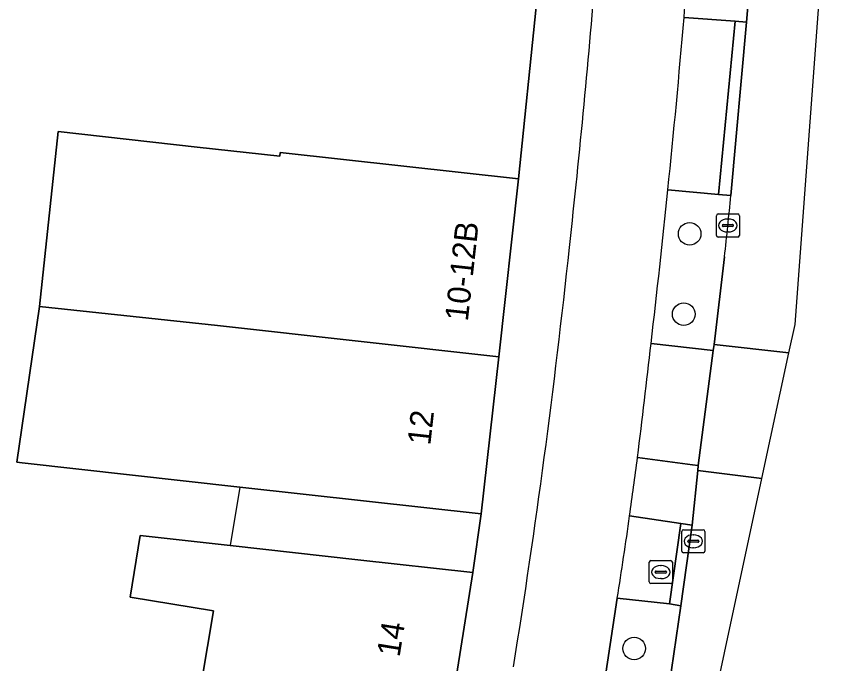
# Model space of a CAD drawing. Extents: x 161087 to 161926, y 382572 to 383873.
# Drawn here: x 161833.12 to 161869.18, y 382703.67 to 382731.66 of the extents above; entities that cross this region are included whole.
import ezdxf

# ---------------------------------------------------------------- set-up
doc = ezdxf.new("R2010")
doc.units = 0
for name, color, linetype in [('IMGEO_Berm_gesloten', 7, 'Continuous'), ('IMGEO_Berm_groen', 7, 'Continuous'), ('IMGEO_Berm_open', 7, 'Continuous'), ('IMGEO_Boom', 7, 'Continuous'), ('IMGEO_Erf', 7, 'Continuous'), ('IMGEO_Fietspad_gesloten', 7, 'Continuous'), ('IMGEO_Kolk', 7, 'Continuous'), ('IMGEO_Pand', 7, 'Continuous'), ('IMGEO_Pand_nummerreeks', 7, 'Continuous'), ('IMGEO_Pand_overbouw', 7, 'Continuous'), ('IMGEO_Rijbaan_lokaal_gesloten', 7, 'Continuous'), ('IMGEO_Rijbaan_lokaal_open', 7, 'Continuous'), ('IMGEO_Rioolput', 7, 'Continuous'), ('IMGEO_Voetpad_open', 7, 'Continuous')]:
    doc.layers.add(name, color=color, linetype=linetype)

msp = doc.modelspace()

# ---------------------------------------------------------------- linework, layer by layer
at = {"layer": 'IMGEO_Berm_gesloten'}
for points in [[(161864.696, 382731.416), (161864.202, 382731.46), (161863.482, 382723.956), (161864.006, 382723.914)], [(161862.334, 382709.651), (161861.851, 382709.721), (161861.36, 382706.245), (161861.855, 382706.161)]]:
    msp.add_lwpolyline(points, close=True, dxfattribs=at)
at = {"layer": 'IMGEO_Berm_groen'}
for points in [[(161861.988, 382731.623), (161864.202, 382731.46), (161864.696, 382731.416), (161864.916, 382734.182), (161865.365, 382740.966)], [(161864.202, 382731.46), (161861.988, 382731.623)], [(161861.289, 382724.163), (161863.482, 382723.956), (161864.202, 382731.46)], [(161864.006, 382723.914), (161863.482, 382723.956), (161861.289, 382724.163)], [(161860.56, 382717.514), (161863.253, 382717.214), (161863.287, 382717.469), (161863.737, 382721.269)], [(161862.582, 382712.012), (161862.605, 382712.233), (161862.359, 382712.264), (161859.973, 382712.583)], [(161859.633, 382710.052), (161861.851, 382709.721), (161862.334, 382709.651), (161862.582, 382712.012)]]:
    msp.add_lwpolyline(points, dxfattribs=at)
msp.add_lwpolyline([(161861.855, 382706.161), (161861.36, 382706.245), (161859.099, 382706.489), (161858.483, 382702.48), (161861.244, 382702.01)], close=True, dxfattribs=at)
for centre, radius, start, end in [((161450.001, 382766.972), 413.501, 355.09598, 355.73945), ((161429.341, 382768.399), 434.207, 354.15268, 355.14138), ((161419.334, 382769.255), 444.249, 353.31171, 354.17439), ((161780.577, 382731.063), 83.735, 353.28328, 355.10254), ((161621.237, 382743.365), 240.713, 352.04509, 352.65295)]:
    msp.add_arc(centre, radius, start, end, dxfattribs=at)
at = {"layer": 'IMGEO_Berm_open'}
for points in [[(161859.973, 382712.583), (161862.359, 382712.264), (161862.605, 382712.233), (161863.253, 382717.214)], [(161863.253, 382717.214), (161860.56, 382717.514)], [(161861.851, 382709.721), (161859.633, 382710.052)], [(161859.099, 382706.489), (161861.36, 382706.245), (161861.851, 382709.721)]]:
    msp.add_lwpolyline(points, dxfattribs=at)
for centre, radius, start, end in [((161529.822, 382754.385), 332.787, 352.78381, 353.63878), ((161657.287, 382738.557), 204.344, 350.97121, 351.98141)]:
    msp.add_arc(centre, radius, start, end, dxfattribs=at)
at = {"layer": 'IMGEO_Boom'}
for centre in [(161862.23, 382722.257), (161861.973, 382718.78), (161859.833, 382704.313)]:
    msp.add_circle(centre, 0.489, dxfattribs=at)
at = {"layer": 'IMGEO_Erf'}
msp.add_lwpolyline([(161841.12, 382702.859), (161841.626, 382705.941), (161838.025, 382706.533), (161838.463, 382709.199), (161842.351, 382708.766), (161847.875, 382708.151), (161852.844, 382707.598), (161853.217, 382710.138), (161848.248, 382710.691), (161842.767, 382711.301), (161833.36, 382712.347), (161833.118, 382712.374), (161834.103, 382719.118), (161834.908, 382726.684), (161840.922, 382726.017), (161844.498, 382725.62), (161844.517, 382725.785), (161849.862, 382725.191), (161854.831, 382724.638), (161855.594, 382732.092)], dxfattribs=at)
at = {"layer": 'IMGEO_Fietspad_gesloten'}
msp.add_lwpolyline([(161857.735, 382697.596), (161858.483, 382702.48), (161859.099, 382706.489)], dxfattribs=at)
for centre, radius, start, end in [((161450.001, 382766.972), 413.501, 355.09598, 355.73945), ((161443.323, 382767.161), 416.2, 353.72536, 355.4368), ((161429.341, 382768.399), 434.207, 354.15268, 355.14138), ((161419.334, 382769.255), 444.249, 353.31171, 354.17439), ((161515.74, 382757.93), 343.21, 350.8781, 353.93592), ((161529.822, 382754.385), 332.787, 352.78381, 353.63878), ((161621.237, 382743.365), 240.713, 352.04509, 352.65295), ((161657.287, 382738.557), 204.344, 350.97121, 351.98141)]:
    msp.add_arc(centre, radius, start, end, dxfattribs=at)
at = {"layer": 'IMGEO_Kolk'}
for p, q in [((161863.384, 382722.194), (161863.384, 382723.046)), ((161863.459, 382723.12), (161864.311, 382723.12)), ((161864.385, 382723.046), (161864.385, 382722.194)), ((161863.643, 382722.614), (161863.643, 382722.626)), ((161863.686, 382722.663), (161864.084, 382722.663)), ((161863.872, 382722.9), (161863.897, 382722.9)), ((161864.127, 382722.626), (161864.127, 382722.614)), ((161864.081, 382722.577), (161863.683, 382722.577)), ((161863.895, 382722.34), (161863.87, 382722.34)), ((161864.311, 382722.12), (161863.459, 382722.12)), ((161861.888, 382708.528), (161861.888, 382709.38)), ((161861.963, 382709.454), (161862.815, 382709.454)), ((161862.889, 382709.38), (161862.889, 382708.528)), ((161862.147, 382708.948), (161862.147, 382708.96)), ((161862.585, 382708.911), (161862.187, 382708.911)), ((161862.19, 382708.997), (161862.588, 382708.997)), ((161862.376, 382709.234), (161862.401, 382709.234)), ((161862.631, 382708.96), (161862.631, 382708.948)), ((161862.399, 382708.674), (161862.374, 382708.674)), ((161862.815, 382708.454), (161861.963, 382708.454))]:
    msp.add_line(p, q, dxfattribs=at)
for points in [[(161863.384, 382722.194), (161863.384, 382723.046)], [(161863.459, 382723.12), (161864.311, 382723.12)], [(161864.385, 382723.046), (161864.385, 382722.194)], [(161864.311, 382722.12), (161863.459, 382722.12)], [(161861.888, 382708.528), (161861.888, 382709.38)], [(161861.963, 382709.454), (161862.815, 382709.454)], [(161862.889, 382709.38), (161862.889, 382708.528)], [(161862.815, 382708.454), (161861.963, 382708.454)]]:
    msp.add_lwpolyline(points, dxfattribs=at)
for centre, radius, start, end in [((161863.461, 382723.044), 0.0765, 91.552, 178.448), ((161863.461, 382723.044), 0.0765, 91.552, 178.448), ((161864.309, 382723.044), 0.0765, 1.552, 88.448), ((161864.309, 382723.044), 0.0765, 1.552, 88.448), ((161863.683, 382722.623), 0.0403, 85.8775, 175.7526), ((161863.68, 382722.613), 0.0366, 178.938, 274.7102), ((161864.084, 382722.62), 0.043, 264.8664, 352.4533), ((161864.088, 382722.625), 0.0386, 1.7309, 96.639), ((161863.461, 382722.196), 0.0765, 181.552, 268.448), ((161863.461, 382722.196), 0.0765, 181.552, 268.448), ((161864.309, 382722.196), 0.0765, 271.552, 358.448), ((161864.309, 382722.196), 0.0765, 271.552, 358.448), ((161861.965, 382709.378), 0.0765, 91.552, 178.448), ((161861.965, 382709.378), 0.0765, 91.552, 178.448), ((161862.813, 382709.378), 0.0765, 1.552, 88.448), ((161862.813, 382709.378), 0.0765, 1.552, 88.448), ((161862.187, 382708.957), 0.0403, 85.8775, 175.7526), ((161862.184, 382708.947), 0.0366, 178.938, 274.7102), ((161862.588, 382708.954), 0.043, 264.8664, 352.4533), ((161862.592, 382708.959), 0.0386, 1.7309, 96.639), ((161861.965, 382708.53), 0.0765, 181.552, 268.448), ((161861.965, 382708.53), 0.0765, 181.552, 268.448), ((161862.813, 382708.53), 0.0765, 271.552, 358.448), ((161862.813, 382708.53), 0.0765, 271.552, 358.448)]:
    msp.add_arc(centre, radius, start, end, dxfattribs=at)
for centre, major_axis, ratio, start_param, end_param in [((161863.871, 382722.62), (-0.387, 0.002), 0.722429, 4.712389, 7.853982), ((161863.896, 382722.62), (-0.39, 0.002), 0.717154, 1.570796, 4.712389), ((161862.375, 382708.954), (-0.387, 0.002), 0.722429, 4.712389, 7.853982), ((161862.4, 382708.954), (-0.39, 0.002), 0.717154, 1.570796, 4.712389)]:
    msp.add_ellipse(centre, major_axis=major_axis, ratio=ratio, start_param=start_param, end_param=end_param, dxfattribs=at)
at = {"layer": 'IMGEO_Pand'}
for points in [[(161854.831, 382724.638), (161849.862, 382725.191), (161844.517, 382725.785), (161844.498, 382725.62), (161840.922, 382726.017), (161834.908, 382726.684), (161834.103, 382719.118), (161841.8, 382718.299), (161853.975, 382716.944)], [(161833.118, 382712.374), (161833.36, 382712.347), (161842.767, 382711.301), (161848.248, 382710.691), (161853.217, 382710.138), (161853.975, 382716.944), (161841.8, 382718.299), (161834.103, 382719.118)], [(161841.12, 382702.859), (161851.814, 382701.048), (161852.844, 382707.598), (161847.875, 382708.151), (161842.351, 382708.766), (161838.463, 382709.199), (161838.025, 382706.533), (161841.626, 382705.941)]]:
    msp.add_lwpolyline(points, close=True, dxfattribs=at)
at = {"layer": 'IMGEO_Pand_overbouw'}
msp.add_lwpolyline([(161852.844, 382707.598), (161853.217, 382710.138), (161848.248, 382710.691), (161842.767, 382711.301), (161842.351, 382708.766), (161847.875, 382708.151)], close=True, dxfattribs=at)
at = {"layer": 'IMGEO_Rijbaan_lokaal_gesloten'}
for points in [[(161866.524, 382717.11), (161866.788, 382718.343), (161869.18, 382750.506), (161865.994, 382750.69), (161865.801, 382747.557), (161865.365, 382740.966), (161864.916, 382734.182), (161864.696, 382731.416), (161864.006, 382723.914)], [(161863.737, 382721.269), (161863.287, 382717.469), (161866.524, 382717.11)], [(161857.368, 382674.342), (161865.358, 382711.665), (161862.582, 382712.012), (161862.334, 382709.651), (161861.855, 382706.161), (161861.244, 382702.01)]]:
    msp.add_lwpolyline(points, dxfattribs=at)
msp.add_arc((161780.577, 382731.063), 83.735, 353.28328, 355.10254, dxfattribs=at)
at = {"layer": 'IMGEO_Rijbaan_lokaal_open'}
msp.add_lwpolyline([(161865.358, 382711.665), (161866.524, 382717.11), (161863.287, 382717.469), (161863.253, 382717.214), (161862.605, 382712.233), (161862.582, 382712.012)], close=True, dxfattribs=at)
at = {"layer": 'IMGEO_Rioolput'}
for p, q in [((161860.48, 382707.194), (161860.48, 382708.046)), ((161860.555, 382708.12), (161861.407, 382708.12)), ((161860.968, 382707.9), (161860.993, 382707.9)), ((161861.481, 382708.046), (161861.481, 382707.194)), ((161860.739, 382707.614), (161860.739, 382707.626)), ((161861.177, 382707.577), (161860.779, 382707.577)), ((161860.782, 382707.663), (161861.18, 382707.663)), ((161861.223, 382707.626), (161861.223, 382707.614)), ((161861.407, 382707.12), (161860.555, 382707.12)), ((161860.991, 382707.34), (161860.966, 382707.34))]:
    msp.add_line(p, q, dxfattribs=at)
for points in [[(161860.48, 382707.194), (161860.48, 382708.046)], [(161860.555, 382708.12), (161861.407, 382708.12)], [(161861.481, 382708.046), (161861.481, 382707.194)], [(161861.407, 382707.12), (161860.555, 382707.12)]]:
    msp.add_lwpolyline(points, dxfattribs=at)
for centre, radius, start, end in [((161860.557, 382708.044), 0.0765, 91.552, 178.448), ((161860.557, 382708.044), 0.0765, 91.552, 178.448), ((161861.405, 382708.044), 0.0765, 1.552, 88.448), ((161861.405, 382708.044), 0.0765, 1.552, 88.448), ((161860.779, 382707.623), 0.0403, 85.8775, 175.7526), ((161860.776, 382707.613), 0.0366, 178.938, 274.7102), ((161861.18, 382707.62), 0.043, 264.8664, 352.4533), ((161861.184, 382707.625), 0.0386, 1.7309, 96.639), ((161860.557, 382707.196), 0.0765, 181.552, 268.448), ((161860.557, 382707.196), 0.0765, 181.552, 268.448), ((161861.405, 382707.196), 0.0765, 271.552, 358.448), ((161861.405, 382707.196), 0.0765, 271.552, 358.448)]:
    msp.add_arc(centre, radius, start, end, dxfattribs=at)
for centre, major_axis, ratio, start_param, end_param in [((161860.967, 382707.62), (-0.387, 0.002), 0.722429, 4.712389, 7.853982), ((161860.992, 382707.62), (-0.39, 0.002), 0.717154, 1.570796, 4.712389)]:
    msp.add_ellipse(centre, major_axis=major_axis, ratio=ratio, start_param=start_param, end_param=end_param, dxfattribs=at)
at = {"layer": 'IMGEO_Voetpad_open'}
msp.add_lwpolyline([(161858.54, 382773.49), (161857.067, 382750), (161856.985, 382748.691), (161856.266, 382740.106), (161855.594, 382732.092), (161854.831, 382724.638), (161853.975, 382716.944), (161853.217, 382710.138), (161852.844, 382707.598), (161851.814, 382701.048), (161850.622, 382693.473), (161850.596, 382693.309), (161849.258, 382686.598), (161847.919, 382679.881), (161847.875, 382679.658), (161846.175, 382671.975), (161844.664, 382665.145)], dxfattribs=at)
for centre, radius, start, end in [((161443.323, 382767.161), 416.2, 353.72536, 355.4368), ((161515.74, 382757.93), 343.21, 350.8781, 353.93592)]:
    msp.add_arc(centre, radius, start, end, dxfattribs=at)

# ---------------------------------------------------------------- texts
at = {"layer": 'IMGEO_Pand_nummerreeks'}
for s, rotation, p in [('10-12B', 83.6518, (161852.633, 382718.447)), ('12', 83.6485, (161851.01, 382713.086)), ('14', 80.7574, (161849.678, 382703.914))]:
    msp.add_text(s, height=1, rotation=rotation, dxfattribs=at).set_placement(p)

doc.saveas('drawing.dxf')
